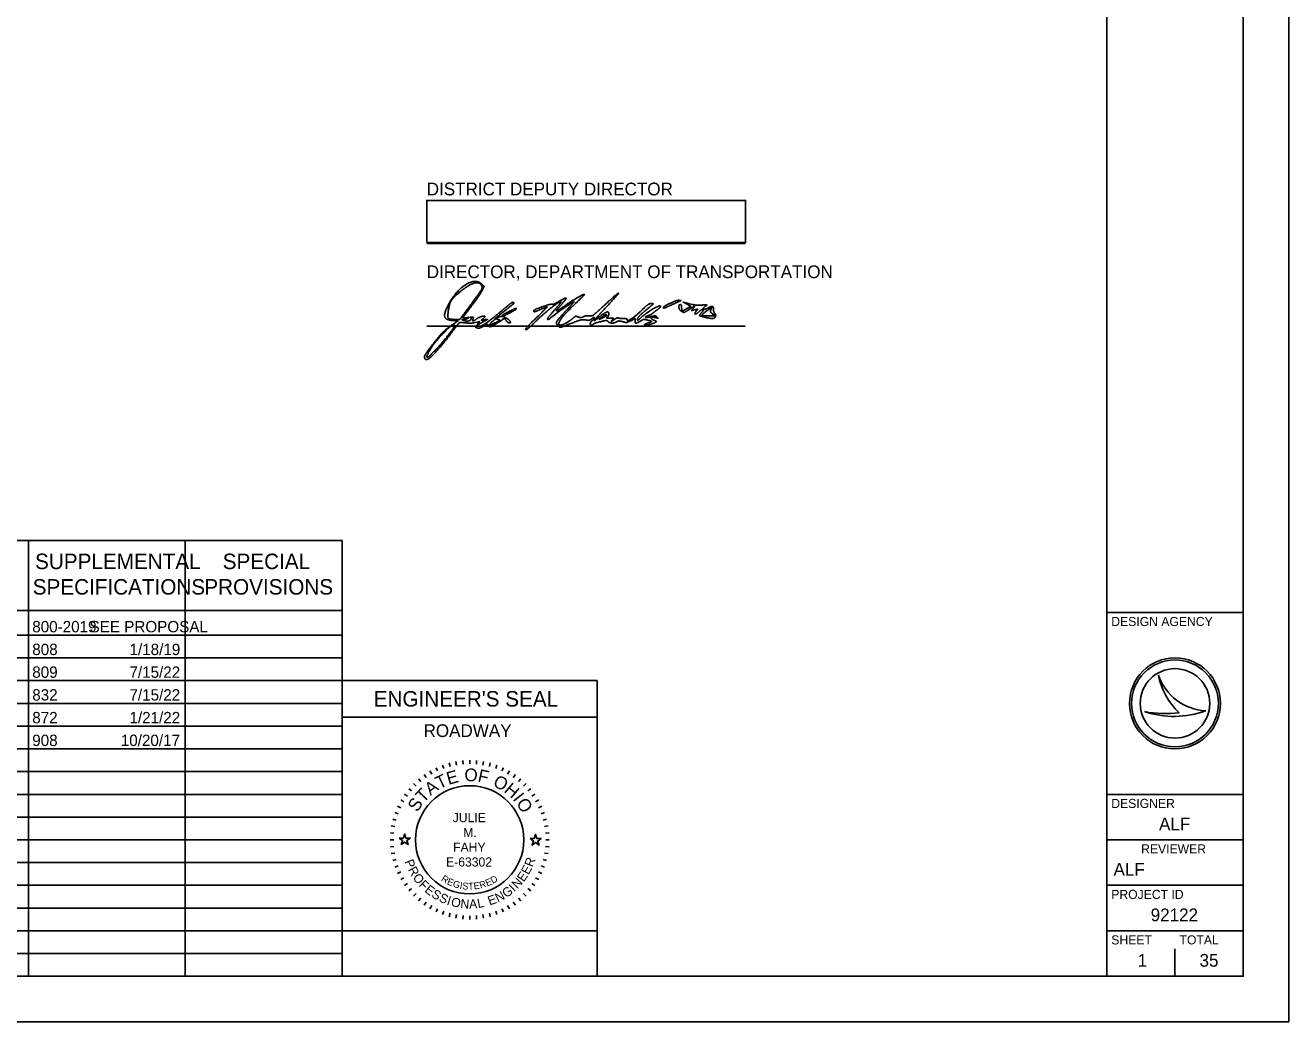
# Model space of a CAD drawing. Extents: x 0 to 34, y 0 to 22.
# Drawn here: x 20.12 to 34, y 0 to 10.96 of the extents above; entities that cross this region are included whole.
import ezdxf

# ---------------------------------------------------------------- set-up
doc = ezdxf.new("R2010")
doc.units = 0
for name, color, linetype in [('SH_Border', 7, 'Continuous'), ('SH_Cut_Line', 7, 'Continuous'), ('SH_Data', 7, 'Continuous'), ('SH_Text', 7, 'Continuous')]:
    doc.layers.add(name, color=color, linetype=linetype)

msp = doc.modelspace()

# ---------------------------------------------------------------- linework, layer by layer
at = {"layer": 'SH_Border'}
for p, q in [((32, 0.5), (32, 21.5)), ((32, 4.5), (33.5, 4.5)), ((32, 2.5), (33.5, 2.5)), ((32, 2), (33.5, 2)), ((32, 1.5), (33.5, 1.5)), ((32, 1), (33.5, 1))]:
    msp.add_line(p, q, dxfattribs=at)
msp.add_lwpolyline([(1.5, 21.5), (33.5, 21.5), (33.5, 0.5), (1.5, 0.5)], close=True, dxfattribs=at)
at = {"layer": 'SH_Cut_Line'}
msp.add_lwpolyline([(0, 0), (34, 0), (34, 22), (0, 22)], close=True, dxfattribs=at)
at = {"layer": 'SH_Data'}
for p, q in [((24.528, 8.555), (28.028, 8.555)), ((24.528, 7.648), (28.028, 7.648)), ((10.15, 5.292), (23.6, 5.292)), ((20.15, 0.5), (20.15, 5.292)), ((21.875, 0.5), (21.875, 5.292)), ((23.6, 0.5), (23.6, 5.292)), ((10.15, 4.521), (23.6, 4.521)), ((10.15, 4.25), (23.6, 4.25)), ((10.15, 4), (23.6, 4)), ((10.15, 3.75), (23.6, 3.75)), ((23.6, 0.5), (23.6, 3.75)), ((23.6, 3.75), (26.4, 3.75)), ((26.4, 3.75), (26.4, 0.5)), ((32.567, 3.81), (32.567, 3.81)), ((10.15, 3.5), (23.6, 3.5)), ((32.75, 3.5), (32.75, 3.5)), ((23.6, 3.35), (26.4, 3.35)), ((32.417, 3.41), (32.417, 3.41)), ((33.087, 3.419), (33.087, 3.419)), ((10.15, 3.25), (23.6, 3.25)), ((10.15, 3), (23.6, 3)), ((24.63, 2.793), (24.647, 2.757)), ((24.701, 2.822), (24.714, 2.785)), ((24.774, 2.845), (24.784, 2.807)), ((24.848, 2.862), (24.855, 2.822)), ((24.924, 2.872), (24.927, 2.832)), ((25, 2.875), (25, 2.835)), ((25.076, 2.872), (25.073, 2.832)), ((25.152, 2.862), (25.145, 2.822)), ((25.226, 2.845), (25.216, 2.807)), ((25.299, 2.822), (25.286, 2.785)), ((25.37, 2.793), (25.353, 2.757)), ((10.15, 2.75), (23.6, 2.75)), ((24.438, 2.67), (24.463, 2.64)), ((24.498, 2.717), (24.521, 2.684)), ((24.563, 2.758), (24.583, 2.723)), ((25.437, 2.758), (25.417, 2.723)), ((25.502, 2.717), (25.479, 2.684)), ((25.562, 2.67), (25.537, 2.64)), ((10.15, 2.5), (23.6, 2.5)), ((24.283, 2.502), (24.316, 2.479)), ((24.33, 2.562), (24.36, 2.537)), ((24.381, 2.619), (24.41, 2.59)), ((25.619, 2.619), (25.59, 2.59)), ((25.67, 2.562), (25.64, 2.537)), ((25.717, 2.502), (25.684, 2.479)), ((24.207, 2.37), (24.243, 2.353)), ((24.242, 2.438), (24.277, 2.418)), ((25.758, 2.438), (25.723, 2.418)), ((25.793, 2.37), (25.757, 2.353)), ((10.15, 2.25), (23.6, 2.25)), ((24.155, 2.226), (24.193, 2.216)), ((24.178, 2.299), (24.215, 2.286)), ((25.822, 2.299), (25.785, 2.286)), ((25.845, 2.226), (25.807, 2.216)), ((24.138, 2.152), (24.178, 2.145)), ((25.862, 2.152), (25.822, 2.145)), ((10.15, 2), (23.6, 2)), ((24.125, 2), (24.165, 2)), ((24.128, 2.076), (24.168, 2.073)), ((25.872, 2.076), (25.832, 2.073)), ((25.875, 2), (25.835, 2)), ((24.128, 1.924), (24.168, 1.927)), ((24.138, 1.848), (24.178, 1.855)), ((25.862, 1.848), (25.822, 1.855)), ((25.872, 1.924), (25.832, 1.927)), ((10.15, 1.75), (23.6, 1.75)), ((24.155, 1.774), (24.193, 1.784)), ((24.178, 1.701), (24.215, 1.714)), ((25.822, 1.701), (25.785, 1.714)), ((25.845, 1.774), (25.807, 1.784)), ((24.207, 1.63), (24.243, 1.647)), ((24.242, 1.563), (24.277, 1.583)), ((25.758, 1.563), (25.723, 1.583)), ((25.793, 1.63), (25.757, 1.647)), ((10.15, 1.5), (23.6, 1.5)), ((24.283, 1.498), (24.316, 1.521)), ((24.33, 1.438), (24.36, 1.463)), ((24.381, 1.381), (24.41, 1.41)), ((25.619, 1.381), (25.59, 1.41)), ((25.67, 1.438), (25.64, 1.463)), ((25.717, 1.498), (25.684, 1.521)), ((10.15, 1.25), (23.6, 1.25)), ((24.438, 1.33), (24.463, 1.36)), ((24.498, 1.283), (24.521, 1.316)), ((24.563, 1.242), (24.583, 1.277)), ((25.437, 1.242), (25.417, 1.277)), ((25.502, 1.283), (25.479, 1.316)), ((25.562, 1.33), (25.537, 1.36)), ((24.63, 1.207), (24.647, 1.243)), ((24.701, 1.178), (24.714, 1.215)), ((24.774, 1.155), (24.784, 1.193)), ((24.848, 1.138), (24.855, 1.178)), ((24.924, 1.128), (24.927, 1.168)), ((25, 1.125), (25, 1.165)), ((25.076, 1.128), (25.073, 1.168)), ((25.152, 1.138), (25.145, 1.178)), ((25.226, 1.155), (25.216, 1.193)), ((25.299, 1.178), (25.286, 1.215)), ((25.37, 1.207), (25.353, 1.243)), ((10.15, 1), (23.6, 1)), ((10.15, 0.75), (23.6, 0.75)), ((32.75, 0.5), (32.75, 0.8)), ((32.375, 0.675), (32.375, 0.675)), ((23.6, 0.5), (26.4, 0.5))]:
    msp.add_line(p, q, dxfattribs=at)
for points in [[(24.528, 8.565), (24.528, 9.03), (28.032, 9.03), (28.032, 8.565)], [(24.224, 2.02), (24.271, 2.02), (24.285, 2.065), (24.299, 2.02), (24.346, 2.02), (24.308, 1.992), (24.323, 1.948), (24.285, 1.975), (24.247, 1.948), (24.262, 1.992)], [(25.663, 2.015), (25.71, 2.015), (25.724, 2.059), (25.739, 2.015), (25.785, 2.015), (25.748, 1.987), (25.762, 1.942), (25.724, 1.97), (25.686, 1.942), (25.701, 1.987)], [(23.6, 0.5), (23.6, 1), (26.4, 1), (26.4, 0.5)]]:
    msp.add_lwpolyline(points, close=True, dxfattribs=at)
for centre, radius in [((32.75, 3.5), 0.5), ((32.75, 3.5), 0.477), ((32.75, 3.5), 0.477), ((32.75, 3.5), 0.382), ((25, 2), 0.595)]:
    msp.add_circle(centre, radius, dxfattribs=at)
for centre, radius, start, end in [((33.116, 3.998), 0.58, 198.9257, 198.9319), ((33.347, 3.97), 0.796, 191.6379, 191.6421), ((33.116, 3.998), 0.58, 198.9319, 267.1657), ((33.347, 3.97), 0.796, 191.6421, 226.0947), ((32.739, 4.37), 1.013, 251.4576, 290.0832), ((32.648, 4.654), 1.266, 259.4964, 259.4995), ((32.739, 4.37), 1.013, 251.4527, 251.4576), ((32.648, 4.654), 1.266, 259.4995, 276.6672)]:
    msp.add_arc(centre, radius, start, end, dxfattribs=at)
at = {"layer": 'SH_Text'}
for p, q in [((24.99, 7.853), (24.99, 7.853)), ((27.129, 7.852), (27.129, 7.852)), ((25.311, 7.722), (25.311, 7.722)), ((25.356, 7.763), (25.356, 7.763)), ((25.727, 7.734), (25.727, 7.734)), ((26.504, 7.765), (26.504, 7.765)), ((27.582, 7.746), (27.582, 7.746)), ((24.62, 7.381), (24.62, 7.381)), ((24.504, 7.314), (24.504, 7.314))]:
    msp.add_line(p, q, dxfattribs=at)
for points in [[(27.393, 7.843), (27.43, 7.864), (27.389, 7.887)], [(27.642, 7.759), (27.698, 7.759), (27.669, 7.782)], [(24.843, 7.686), (24.873, 7.708), (24.835, 7.708)], [(25.085, 7.666), (25.107, 7.699), (25.065, 7.689)], [(26.453, 7.746), (26.423, 7.72), (26.464, 7.74)]]:
    msp.add_lwpolyline(points, dxfattribs=at)
for points in [[(24.779, 7.904), (24.865, 8.054), (25.073, 8.17), (25.139, 8.105)], [(25.13, 8.096), (25.104, 8.138), (24.978, 8.096), (24.883, 8.015)], [(24.99, 7.853), (25.112, 8.017), (25.144, 8.073), (25.13, 8.096)], [(25.139, 8.105), (25.158, 8.086), (25.158, 8.081), (25.139, 8.043)], [(24.883, 8.015), (24.816, 7.958), (24.777, 7.894), (24.766, 7.822)], [(25.139, 8.043), (25.128, 8.02), (25.077, 7.944), (25.024, 7.875)], [(26.002, 7.916), (25.992, 7.925), (25.782, 7.758), (25.704, 7.679)], [(26.142, 7.915), (26.093, 7.888), (25.905, 7.755), (25.891, 7.739)], [(25.908, 7.887), (25.914, 7.885), (25.943, 7.898), (25.974, 7.916)], [(25.924, 7.815), (25.97, 7.867), (26.005, 7.912), (26.002, 7.916)], [(25.974, 7.916), (26.052, 7.962), (26.065, 7.949), (26.005, 7.882)], [(26.033, 7.862), (26.113, 7.919), (26.244, 7.996), (26.26, 7.996)], [(26.077, 7.836), (26.123, 7.886), (26.152, 7.921), (26.142, 7.915)], [(26.26, 7.996), (26.265, 7.996), (26.224, 7.954), (26.168, 7.902)], [(26.487, 7.883), (26.562, 7.952), (26.628, 8.009), (26.634, 8.009)], [(26.634, 8.009), (26.639, 8.009), (26.587, 7.949), (26.518, 7.875)], [(27.129, 7.852), (27.129, 7.865), (27.282, 7.935), (27.301, 7.931)], [(27.301, 7.931), (27.322, 7.927), (27.323, 7.928), (27.201, 7.873)], [(24.835, 7.708), (24.737, 7.71), (24.714, 7.791), (24.779, 7.904)], [(24.766, 7.822), (24.755, 7.749), (24.776, 7.721), (24.844, 7.721)], [(24.844, 7.721), (24.891, 7.721), (24.895, 7.725), (24.99, 7.853)], [(25.024, 7.875), (24.972, 7.805), (24.929, 7.745), (24.929, 7.74)], [(25.108, 7.646), (25.131, 7.646), (25.257, 7.735), (25.369, 7.831)], [(25.386, 7.816), (25.293, 7.743), (25.271, 7.722), (25.315, 7.745)], [(25.356, 7.763), (25.376, 7.781), (25.508, 7.847), (25.513, 7.842)], [(25.513, 7.842), (25.519, 7.836), (25.377, 7.759), (25.359, 7.759)], [(25.369, 7.831), (25.419, 7.873), (25.465, 7.909), (25.47, 7.909)], [(25.47, 7.909), (25.495, 7.909), (25.472, 7.884), (25.386, 7.816)], [(25.705, 7.818), (25.705, 7.829), (25.892, 7.892), (25.908, 7.887)], [(25.786, 7.834), (25.723, 7.807), (25.704, 7.803), (25.705, 7.818)], [(25.727, 7.734), (25.798, 7.803), (25.854, 7.859), (25.85, 7.859)], [(25.85, 7.859), (25.847, 7.859), (25.818, 7.848), (25.786, 7.834)], [(25.858, 7.721), (25.848, 7.721), (25.877, 7.763), (25.924, 7.815)], [(26.005, 7.882), (25.977, 7.85), (25.954, 7.82), (25.954, 7.816)], [(25.954, 7.816), (25.954, 7.811), (25.99, 7.832), (26.033, 7.862)], [(25.97, 7.651), (25.945, 7.676), (25.973, 7.726), (26.077, 7.836)], [(26.168, 7.902), (26.069, 7.808), (25.979, 7.7), (25.979, 7.673)], [(26.312, 7.761), (26.345, 7.758), (26.369, 7.774), (26.487, 7.883)], [(26.518, 7.875), (26.388, 7.737), (26.356, 7.69), (26.439, 7.758)], [(26.439, 7.758), (26.487, 7.798), (26.529, 7.808), (26.529, 7.78)], [(26.504, 7.765), (26.504, 7.779), (26.48, 7.77), (26.453, 7.746)], [(26.529, 7.78), (26.529, 7.771), (26.523, 7.757), (26.514, 7.749)], [(26.729, 7.72), (26.729, 7.697), (26.825, 7.758), (26.895, 7.827)], [(26.967, 7.849), (26.893, 7.788), (26.842, 7.734), (26.842, 7.718)], [(26.876, 7.735), (26.93, 7.784), (27.077, 7.874), (27.094, 7.869)], [(26.895, 7.827), (26.94, 7.87), (26.977, 7.896), (26.995, 7.896)], [(26.995, 7.896), (27.019, 7.895), (27.016, 7.889), (26.967, 7.849)], [(27.004, 7.782), (27.001, 7.778), (26.986, 7.771), (26.97, 7.766)], [(27.06, 7.827), (27.033, 7.807), (27.008, 7.787), (27.004, 7.782)], [(27.094, 7.869), (27.102, 7.866), (27.087, 7.847), (27.06, 7.827)], [(27.201, 7.873), (27.138, 7.845), (27.129, 7.842), (27.129, 7.852)], [(27.33, 7.808), (27.304, 7.822), (27.293, 7.884), (27.317, 7.884)], [(27.317, 7.884), (27.324, 7.884), (27.329, 7.87), (27.329, 7.853)], [(27.329, 7.853), (27.329, 7.816), (27.344, 7.814), (27.393, 7.843)], [(27.405, 7.827), (27.365, 7.8), (27.352, 7.797), (27.33, 7.808)], [(27.389, 7.887), (27.346, 7.911), (27.345, 7.911), (27.448, 7.885)], [(27.453, 7.838), (27.477, 7.868), (27.461, 7.864), (27.405, 7.827)], [(27.472, 7.826), (27.439, 7.818), (27.437, 7.819), (27.453, 7.838)], [(27.448, 7.885), (27.469, 7.88), (27.514, 7.877), (27.548, 7.879)], [(27.492, 7.816), (27.507, 7.833), (27.505, 7.834), (27.472, 7.826)], [(27.521, 7.807), (27.489, 7.777), (27.466, 7.784), (27.492, 7.816)], [(27.546, 7.794), (27.577, 7.828), (27.555, 7.839), (27.521, 7.807)], [(27.582, 7.746), (27.527, 7.759), (27.522, 7.767), (27.546, 7.794)], [(27.548, 7.879), (27.603, 7.882), (27.608, 7.88), (27.588, 7.866)], [(27.589, 7.804), (27.546, 7.773), (27.563, 7.759), (27.642, 7.759)], [(27.588, 7.866), (27.559, 7.844), (27.582, 7.828), (27.616, 7.846)], [(27.65, 7.827), (27.66, 7.853), (27.651, 7.85), (27.589, 7.804)], [(27.616, 7.846), (27.656, 7.867), (27.679, 7.862), (27.679, 7.83)], [(27.669, 7.782), (27.649, 7.797), (27.643, 7.81), (27.65, 7.827)], [(27.679, 7.83), (27.679, 7.814), (27.686, 7.795), (27.694, 7.787)], [(27.694, 7.787), (27.701, 7.779), (27.704, 7.764), (27.7, 7.753)], [(24.835, 7.657), (24.814, 7.678), (24.596, 7.452), (24.55, 7.362)], [(24.592, 7.444), (24.669, 7.545), (24.749, 7.622), (24.843, 7.686)], [(24.62, 7.381), (24.687, 7.45), (24.843, 7.649), (24.835, 7.657)], [(24.924, 7.686), (24.89, 7.69), (24.879, 7.679), (24.802, 7.578)], [(24.936, 7.721), (24.913, 7.72), (24.914, 7.719), (24.94, 7.708)], [(25.065, 7.689), (25.025, 7.679), (25.002, 7.679), (24.924, 7.686)], [(24.929, 7.74), (24.929, 7.735), (24.945, 7.735), (24.964, 7.739)], [(24.979, 7.734), (24.969, 7.727), (24.949, 7.721), (24.936, 7.721)], [(24.94, 7.708), (24.97, 7.696), (25.026, 7.721), (25.009, 7.738)], [(24.964, 7.739), (24.989, 7.745), (24.993, 7.744), (24.979, 7.734)], [(25.009, 7.738), (25.004, 7.743), (25.01, 7.746), (25.022, 7.746)], [(25.022, 7.746), (25.037, 7.746), (25.042, 7.74), (25.037, 7.728)], [(25.037, 7.728), (25.029, 7.704), (25.041, 7.704), (25.074, 7.726)], [(25.084, 7.626), (25.066, 7.633), (25.066, 7.637), (25.085, 7.666)], [(25.074, 7.726), (25.102, 7.746), (25.167, 7.763), (25.167, 7.751)], [(25.151, 7.646), (25.125, 7.631), (25.095, 7.622), (25.084, 7.626)], [(25.152, 7.697), (25.101, 7.669), (25.081, 7.646), (25.108, 7.646)], [(25.145, 7.727), (25.126, 7.713), (25.128, 7.712), (25.161, 7.717)], [(25.167, 7.751), (25.167, 7.747), (25.157, 7.736), (25.145, 7.727)], [(25.202, 7.66), (25.199, 7.669), (25.18, 7.663), (25.151, 7.646)], [(25.161, 7.717), (25.198, 7.722), (25.198, 7.722), (25.152, 7.697)], [(25.316, 7.69), (25.248, 7.645), (25.21, 7.636), (25.202, 7.66)], [(25.258, 7.705), (25.213, 7.665), (25.225, 7.656), (25.283, 7.685)], [(25.311, 7.722), (25.293, 7.728), (25.277, 7.723), (25.258, 7.705)], [(25.283, 7.685), (25.329, 7.709), (25.333, 7.714), (25.311, 7.722)], [(25.315, 7.745), (25.328, 7.752), (25.351, 7.754), (25.368, 7.75)], [(25.401, 7.709), (25.384, 7.733), (25.382, 7.732), (25.316, 7.69)], [(25.359, 7.759), (25.354, 7.759), (25.353, 7.761), (25.356, 7.763)], [(25.368, 7.75), (25.404, 7.741), (25.463, 7.684), (25.436, 7.684)], [(25.436, 7.684), (25.426, 7.684), (25.411, 7.695), (25.401, 7.709)], [(25.617, 7.61), (25.607, 7.61), (25.656, 7.666), (25.727, 7.734)], [(25.704, 7.679), (25.667, 7.641), (25.627, 7.609), (25.617, 7.61)], [(25.891, 7.739), (25.883, 7.729), (25.868, 7.721), (25.858, 7.721)], [(26.169, 7.698), (26.023, 7.641), (25.988, 7.632), (25.97, 7.651)], [(25.979, 7.673), (25.979, 7.665), (25.988, 7.659), (25.998, 7.659)], [(25.998, 7.659), (26.019, 7.659), (26.101, 7.704), (26.137, 7.736)], [(26.137, 7.736), (26.157, 7.754), (26.17, 7.757), (26.194, 7.748)], [(26.275, 7.715), (26.246, 7.719), (26.206, 7.713), (26.169, 7.698)], [(26.194, 7.748), (26.214, 7.74), (26.233, 7.741), (26.249, 7.75)], [(26.249, 7.75), (26.262, 7.758), (26.291, 7.762), (26.312, 7.761)], [(26.344, 7.73), (26.329, 7.716), (26.307, 7.711), (26.275, 7.715)], [(26.341, 7.659), (26.323, 7.659), (26.327, 7.692), (26.348, 7.709)], [(26.359, 7.669), (26.356, 7.664), (26.348, 7.659), (26.341, 7.659)], [(26.367, 7.737), (26.367, 7.744), (26.357, 7.741), (26.344, 7.73)], [(26.348, 7.709), (26.359, 7.717), (26.367, 7.73), (26.367, 7.737)], [(26.436, 7.696), (26.397, 7.687), (26.363, 7.675), (26.359, 7.669)], [(26.52, 7.698), (26.509, 7.71), (26.489, 7.709), (26.436, 7.696)], [(26.464, 7.74), (26.486, 7.751), (26.504, 7.762), (26.504, 7.765)], [(26.514, 7.749), (26.503, 7.737), (26.509, 7.734), (26.541, 7.734)], [(26.616, 7.696), (26.585, 7.679), (26.538, 7.681), (26.52, 7.698)], [(26.541, 7.734), (26.579, 7.734), (26.581, 7.732), (26.565, 7.712)], [(26.565, 7.712), (26.553, 7.697), (26.56, 7.699), (26.587, 7.718)], [(26.587, 7.718), (26.609, 7.733), (26.629, 7.742), (26.633, 7.738)], [(26.681, 7.696), (26.654, 7.704), (26.631, 7.704), (26.616, 7.696)], [(26.633, 7.738), (26.637, 7.735), (26.66, 7.731), (26.685, 7.731)], [(26.77, 7.707), (26.732, 7.689), (26.714, 7.686), (26.681, 7.696)], [(26.685, 7.731), (26.709, 7.731), (26.729, 7.726), (26.729, 7.72)], [(26.817, 7.707), (26.817, 7.73), (26.816, 7.73), (26.77, 7.707)], [(26.879, 7.704), (26.834, 7.678), (26.817, 7.678), (26.817, 7.707)], [(26.842, 7.718), (26.842, 7.71), (26.857, 7.718), (26.876, 7.735)], [(26.962, 7.712), (26.923, 7.722), (26.906, 7.721), (26.879, 7.704)], [(26.998, 7.671), (26.952, 7.656), (26.904, 7.662), (26.948, 7.677)], [(26.97, 7.766), (26.921, 7.75), (26.94, 7.737), (26.992, 7.751)], [(26.948, 7.677), (26.962, 7.682), (26.982, 7.689), (26.992, 7.693)], [(26.992, 7.693), (27.003, 7.697), (26.992, 7.705), (26.962, 7.712)], [(26.992, 7.751), (27.03, 7.761), (27.045, 7.76), (27.058, 7.748)], [(27.039, 7.741), (27.002, 7.75), (26.989, 7.727), (27.023, 7.713)], [(27.023, 7.713), (27.054, 7.702), (27.045, 7.687), (26.998, 7.671)], [(27.058, 7.748), (27.07, 7.735), (27.067, 7.734), (27.039, 7.741)], [(27.7, 7.753), (27.692, 7.732), (27.651, 7.73), (27.582, 7.746)], [(24.802, 7.578), (24.65, 7.376), (24.504, 7.247), (24.504, 7.314)], [(24.504, 7.314), (24.504, 7.324), (24.544, 7.382), (24.592, 7.444)], [(24.55, 7.362), (24.518, 7.301), (24.55, 7.309), (24.62, 7.381)]]:
    msp.add_open_spline(points, degree=2, dxfattribs=at)

# ---------------------------------------------------------------- texts
at = {"layer": 'SH_Data'}
for s, height, p in [('DESIGN AGENCY', 0.1, (32.05, 4.35)), ("ENGINEER'S SEAL", 0.17, (23.945, 3.465)), ('ROADWAY', 0.14, (24.493, 3.13)), ('DESIGNER', 0.1, (32.05, 2.35)), ('JULIE', 0.1, (24.813, 2.194)), ('ALF', 0.14, (32.575, 2.105)), ('M.', 0.1, (24.929, 2.031)), ('FAHY', 0.1, (24.818, 1.869)), ('REVIEWER', 0.1, (32.378, 1.85)), ('E-63302', 0.1, (24.74, 1.706)), ('ALF', 0.14, (32.075, 1.605)), ('PROJECT ID', 0.1, (32.05, 1.35)), ('92122', 0.14, (32.483, 1.105)), ('SHEET', 0.1, (32.05, 0.85)), ('TOTAL', 0.1, (32.8, 0.85)), ('1', 0.14, (32.339, 0.605)), ('35', 0.14, (33.02, 0.605))]:
    msp.add_text(s, height=height, dxfattribs=at).set_placement(p)
for s, height, rotation, p in [('O', 0.14, 359.7812, (24.942, 2.644)), ('T', 0.14, 25.7167, (24.666, 2.554)), ('E', 0.14, 15.7571, (24.767, 2.603)), ('F', 0.14, 347.4362, (25.081, 2.642)), ('O', 0.14, 332.2586, (25.246, 2.598)), ('T', 0.14, 46.4344, (24.492, 2.4)), ('A', 0.14, 36.4747, (24.569, 2.482)), ('H', 0.14, 319.9136, (25.368, 2.532)), ('I', 0.14, 308.367, (25.467, 2.447)), ('S', 0.14, 57.1924, (24.426, 2.298)), ('O', 0.14, 303.1491, (25.506, 2.403)), ('P', 0.1, 291.494, (24.282, 1.762)), ('R', 0.1, 298.7311, (24.318, 1.673)), ('E', 0.1, 61.9951, (25.647, 1.609)), ('R', 0.1, 69.2322, (25.691, 1.694)), ('O', 0.1, 306.4666, (24.368, 1.585)), ('F', 0.1, 314.7068, (24.434, 1.498)), ('R', 0.075, 327.8239, (24.68, 1.554)), ('E', 0.075, 337.7777, (24.744, 1.513)), ('G', 0.075, 344.2727, (24.808, 1.485)), ('I', 0.075, 350.6464, (24.887, 1.463)), ('S', 0.075, 353.7858, (24.915, 1.458)), ('T', 0.075, 3.0061, (24.985, 1.451)), ('E', 0.075, 8.9826, (25.049, 1.453)), ('R', 0.075, 17.6836, (25.119, 1.463)), ('E', 0.075, 23.3052, (25.191, 1.486)), ('D', 0.075, 31.466, (25.255, 1.514)), ('N', 0.1, 47.0224, (25.524, 1.455)), ('E', 0.1, 54.758, (25.593, 1.531)), ('E', 0.1, 321.4393, (24.497, 1.435)), ('S', 0.1, 328.6764, (24.572, 1.377)), ('S', 0.1, 335.9134, (24.654, 1.328)), ('E', 0.1, 20.0742, (25.22, 1.277)), ('N', 0.1, 27.3113, (25.31, 1.31)), ('G', 0.1, 35.0469, (25.4, 1.358)), ('I', 0.1, 43.287, (25.488, 1.422)), ('I', 0.1, 343.1505, (24.742, 1.289)), ('O', 0.1, 346.8859, (24.788, 1.274)), ('N', 0.1, 355.1261, (24.895, 1.251)), ('A', 0.1, 2.8617, (24.996, 1.244)), ('L', 0.1, 10.0987, (25.092, 1.249))]:
    msp.add_text(s, height=height, rotation=rotation, dxfattribs=at).set_placement(p)
at = {"layer": 'SH_Text'}
for s, height, p in [('DISTRICT DEPUTY DIRECTOR', 0.14, (24.528, 9.085)), ('DIRECTOR, DEPARTMENT OF TRANSPORTATION', 0.14, (24.528, 8.175)), ('SUPPLEMENTAL', 0.17, (20.224, 4.976)), ('SPECIAL', 0.17, (22.286, 4.976)), ('SPECIFICATIONS', 0.17, (20.198, 4.696)), ('PROVISIONS', 0.17, (22.084, 4.696)), ('800-2019', 0.125, (20.193, 4.281)), ('SEE PROPOSAL', 0.125, (20.823, 4.281)), ('808', 0.125, (20.193, 4.031)), ('1/18/19', 0.125, (21.262, 4.031)), ('809', 0.125, (20.193, 3.781)), ('7/15/22', 0.125, (21.261, 3.781)), ('832', 0.125, (20.193, 3.531)), ('7/15/22', 0.125, (21.261, 3.531)), ('872', 0.125, (20.193, 3.281)), ('1/21/22', 0.125, (21.261, 3.281)), ('908', 0.125, (20.193, 3.031)), ('10/20/17', 0.125, (21.166, 3.031))]:
    msp.add_text(s, height=height, dxfattribs=at).set_placement(p)

doc.saveas('drawing.dxf')
